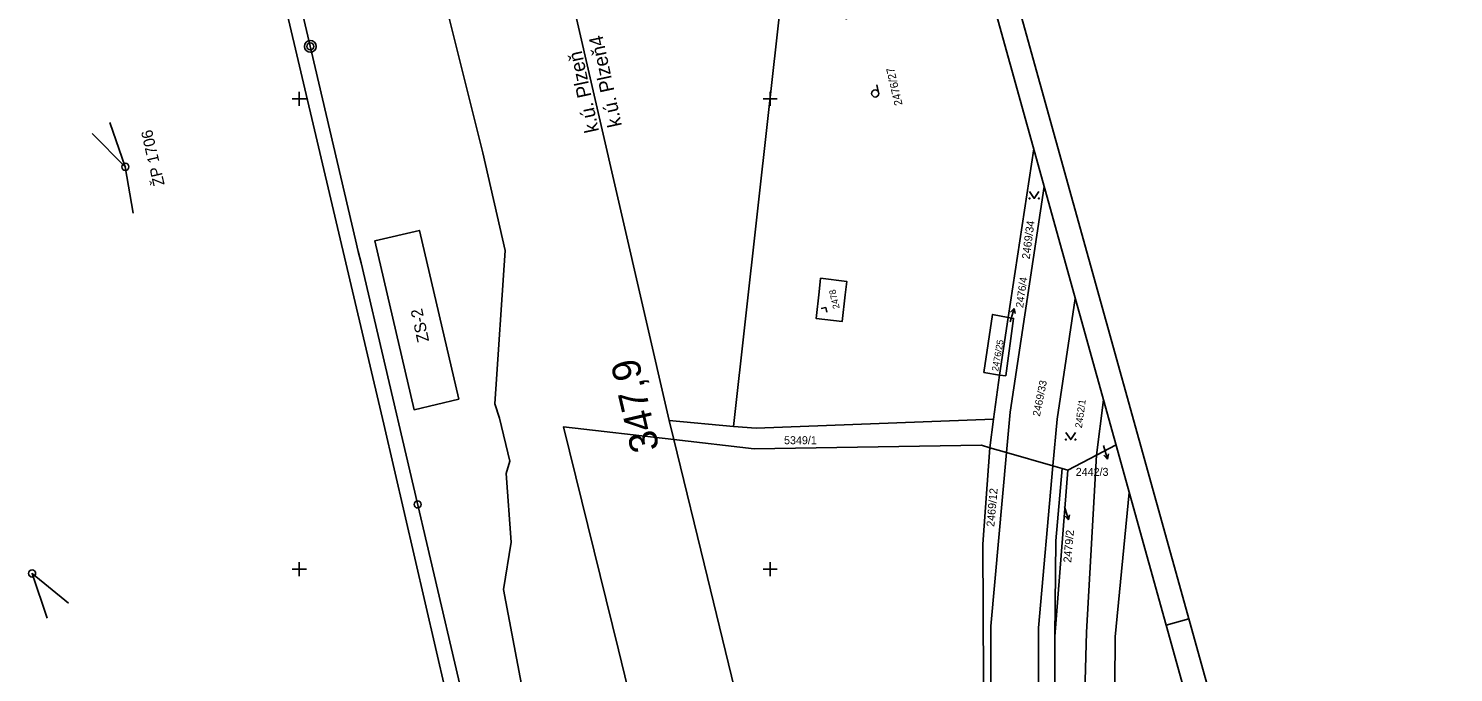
# Model space of a CAD drawing. Extents: x -821122 to -820555, y -1070892 to -1069801.
# Drawn here: x -820857.5 to -820554.8, y -1070622 to -1070485 of the extents above; entities that cross this region are included whole.
import ezdxf

# ---------------------------------------------------------------- set-up
doc = ezdxf.new("R2010")
doc.units = 0
for name, color, linetype in [('Hranice drážního pozemku', 7, 'Continuous'), ('Hranice kat_území', 7, 'Continuous'), ('Hranice parcel', 7, 'Continuous'), ('Katastrální hranice', 7, 'Continuous'), ('Osa staničení koleje', 7, 'Continuous'), ('Parcelní čísla', 7, 'Continuous'), ('Pop  PČ popisy', 7, 'Continuous'), ('Ram', 7, 'Continuous'), ('Sttaniceni a namezniky', 7, 'Continuous'), ('Vrstva 61', 7, 'Continuous'), ('Vrstva 63', 7, 'Continuous'), ('ZBP', 7, 'Continuous'), ('Značky kultur', 7, 'Continuous')]:
    doc.layers.add(name, color=color, linetype=linetype)

msp = doc.modelspace()

# ---------------------------------------------------------------- linework, layer by layer
at = {"layer": 'Hranice drážního pozemku'}
for p, q in [((-820751, -1070439.83), (-820721.42, -1070568.42)), ((-820721.42, -1070568.42), (-820720.44, -1070572.46))]:
    msp.add_line(p, q, dxfattribs=at)
msp.add_lwpolyline([(-820720.44, -1070572.46), (-820743.88, -1070569.76), (-820732.22, -1070617.16), (-820718.37, -1070673.87), (-820707.85, -1070716.96), (-820694.56, -1070770.81), (-820679.24, -1070835.68), (-820677.73, -1070841.82)], dxfattribs=at)
at = {"layer": 'Hranice parcel'}
for p, q in [((-820649.43, -1070546.51), (-820651.29, -1070558.74)), ((-820652.51, -1070568.14), (-820651.29, -1070558.74)), ((-820707.79, -1070569.63), (-820721.42, -1070568.42)), ((-820652.51, -1070568.14), (-820653.29, -1070574.2)), ((-820636.74, -1070578.97), (-820639.52, -1070614.28))]:
    msp.add_line(p, q, dxfattribs=at)
for points in [[(-820707.79, -1070569.63), (-820697.8, -1070480), (-820683.7, -1070483), (-820674.9, -1070430.61)], [(-820649.43, -1070546.51), (-820643.99, -1070510.67)], [(-820641.78, -1070518.63), (-820649.02, -1070566.6), (-820649.79, -1070575.18)], [(-820689.28, -1070538.15), (-820689.6, -1070541.01), (-820690.24, -1070546.7), (-820684.68, -1070547.33), (-820684.04, -1070541.64), (-820683.72, -1070538.82), (-820689.28, -1070538.15)], [(-820635.16, -1070542.44), (-820639.05, -1070568.09), (-820639.94, -1070578.04)], [(-820649.43, -1070546.51), (-820652.73, -1070545.82), (-820654.58, -1070558.16), (-820651.29, -1070558.74)], [(-820649.43, -1070546.51), (-820648.26, -1070546.67), (-820649.94, -1070558.89), (-820651.29, -1070558.74)], [(-820630.65, -1070575.77), (-820629.17, -1070564.01)], [(-820720.44, -1070572.46), (-820743.88, -1070569.76), (-820732.22, -1070617.16), (-820718.37, -1070673.87), (-820707.85, -1070716.96), (-820694.56, -1070770.81), (-820679.24, -1070835.68), (-820677.73, -1070841.82)], [(-820652.51, -1070568.14), (-820702.97, -1070570.05), (-820707.79, -1070569.63)], [(-820644.99, -1070832.73), (-820651.05, -1070805.08), (-820667.4, -1070753.6), (-820685.24, -1070696.04), (-820706.9, -1070628.02), (-820713.28, -1070601.74), (-820720.44, -1070572.46)], [(-820653.29, -1070574.2), (-820654.8, -1070594.7), (-820654.5, -1070652.3), (-820649.6, -1070705.8), (-820646, -1070731.8), (-820634.1, -1070778.9)], [(-820649.79, -1070575.18), (-820653.1, -1070612.1), (-820653, -1070661.95), (-820650.17, -1070690.23), (-820645.27, -1070726.49), (-820637.71, -1070758.5), (-820633.34, -1070773.88)], [(-820610.37, -1070789.85), (-820621.01, -1070753.33), (-820626.77, -1070725.67), (-820631.06, -1070692.78), (-820633.95, -1070654.83), (-820632.82, -1070613.38), (-820630.65, -1070575.77)], [(-820617.78, -1070779.43), (-820623.84, -1070770.91), (-820627.97, -1070756.18), (-820634.95, -1070726.51), (-820640.2, -1070689.19), (-820643, -1070662.1), (-820643, -1070612.5), (-820639.94, -1070578.04)], [(-820639.52, -1070614.28), (-820639.3, -1070594), (-820637.98, -1070578.61)], [(-820639.52, -1070614.28), (-820639.34, -1070655.55), (-820636.46, -1070693.5), (-820631.68, -1070726.33), (-820625.08, -1070753.87), (-820617.78, -1070779.43)]]:
    msp.add_lwpolyline(points, dxfattribs=at)
at = {"layer": 'Katastrální hranice'}
for p, q in [((-820721.42, -1070568.42), (-820751, -1070439.83)), ((-820720.44, -1070572.46), (-820721.42, -1070568.42)), ((-820703.4, -1070574.43), (-820720.44, -1070572.46)), ((-820655.09, -1070573.64), (-820703.4, -1070574.43)), ((-820653.29, -1070574.2), (-820655.09, -1070573.64)), ((-820649.79, -1070575.18), (-820653.29, -1070574.2)), ((-820639.94, -1070578.04), (-820649.79, -1070575.18)), ((-820636.74, -1070578.97), (-820630.65, -1070575.77)), ((-820626.51, -1070573.59), (-820630.65, -1070575.77)), ((-820637.98, -1070578.61), (-820639.94, -1070578.04)), ((-820636.74, -1070578.97), (-820637.98, -1070578.61))]:
    msp.add_line(p, q, dxfattribs=at)
msp.add_lwpolyline([(-820594.11, -1070818.59), (-820613.15, -1070751.36), (-820619.68, -1070724.73), (-820624.16, -1070691.86), (-820626.98, -1070654.7), (-820626.67, -1070614.41), (-820623.69, -1070583.73)], dxfattribs=at)
at = {"layer": 'Osa staničení koleje'}
msp.add_lwpolyline([(-820761.02, -1070645.41), (-820786.89, -1070534.87), (-820787.46, -1070532.43), (-820788.03, -1070530), (-820808.6, -1070442.09), (-820809.13, -1070439.8), (-820809.67, -1070437.51), (-820820.71, -1070390.32)], dxfattribs=at)
at = {"layer": 'Parcelní čísla'}
for p, q in [((-820629.15, -1070573.7), (-820628.31, -1070576.58)), ((-820628.31, -1070576.58), (-820629.08, -1070575.76)), ((-820628.31, -1070576.58), (-820628.11, -1070575.48)), ((-820637.43, -1070586.64), (-820636.59, -1070589.52)), ((-820636.59, -1070589.52), (-820636.39, -1070588.42)), ((-820636.59, -1070589.52), (-820637.35, -1070588.7))]:
    msp.add_line(p, q, dxfattribs=at)
at = {"layer": 'Pop  PČ popisy'}
for p, q in [((-820649.03, -1070547.43), (-820648.15, -1070544.56)), ((-820648.15, -1070544.56), (-820648.92, -1070545.37)), ((-820648.15, -1070544.56), (-820647.97, -1070545.66))]:
    msp.add_line(p, q, dxfattribs=at)
at = {"layer": 'Ram'}
msp.add_line((-820611.05, -1070610.53), (-820615.87, -1070611.87), dxfattribs=at)
for points in [[(-820835.94, -1069801.19), (-820554.83, -1070812.86)], [(-820839.42, -1069807.35), (-820560.99, -1070809.39)]]:
    msp.add_lwpolyline(points, dxfattribs=at)
at = {"layer": 'Sttaniceni a namezniky'}
for centre, radius in [((-820797.65, -1070488.86), 1.25), ((-820797.65, -1070488.86), 0.752), ((-820774.87, -1070586.23), 0.75)]:
    msp.add_circle(centre, radius, dxfattribs=at)
at = {"layer": 'Vrstva 61'}
for p, q in [((-820801.5, -1070500), (-820798.5, -1070500)), ((-820800, -1070498.5), (-820800, -1070501.5)), ((-820701.5, -1070500), (-820698.5, -1070500)), ((-820700, -1070498.5), (-820700, -1070501.5)), ((-820801.5, -1070600), (-820798.5, -1070600)), ((-820800, -1070598.5), (-820800, -1070601.5)), ((-820701.5, -1070600), (-820698.5, -1070600)), ((-820700, -1070598.5), (-820700, -1070601.5))]:
    msp.add_line(p, q, dxfattribs=at)
at = {"layer": 'Vrstva 63'}
for points in [[(-820782.06, -1070569.19), (-820823.93, -1070391.03)], [(-820774.11, -1070459), (-820761.04, -1070511.47), (-820756.27, -1070532.22), (-820758.47, -1070564.86)], [(-820758.47, -1070564.86), (-820757.45, -1070567.88), (-820755.31, -1070577.01), (-820756.05, -1070579.63), (-820755.02, -1070594.22), (-820756.59, -1070604.3), (-820752.56, -1070625.64)], [(-820766.7, -1070635.67), (-820782.06, -1070569.19)]]:
    msp.add_lwpolyline(points, dxfattribs=at)
msp.add_lwpolyline([(-820766.13, -1070563.88), (-820775.61, -1070566.1), (-820783.95, -1070530.19), (-820774.47, -1070527.98)], close=True, dxfattribs=at)
at = {"layer": 'ZBP'}
for p, q in [((-820836.96, -1070514.46), (-820840.27, -1070505.03)), ((-820836.96, -1070514.46), (-820843.98, -1070507.35)), ((-820836.94, -1070514.51), (-820836.97, -1070514.41)), ((-820836.96, -1070514.46), (-820835.31, -1070524.32)), ((-820856.75, -1070600.96), (-820856.77, -1070600.87)), ((-820856.76, -1070600.91), (-820848.99, -1070607.21)), ((-820856.76, -1070600.91), (-820853.52, -1070610.38))]:
    msp.add_line(p, q, dxfattribs=at)
for centre in [(-820836.96, -1070514.46), (-820856.76, -1070600.91)]:
    msp.add_circle(centre, 0.756, dxfattribs=at)
at = {"layer": 'Značky kultur'}
for p, q in [((-820676.94, -1070498.7), (-820677.34, -1070497)), ((-820688.16, -1070544.37), (-820689.13, -1070544.6)), ((-820687.93, -1070545.35), (-820688.16, -1070544.37))]:
    msp.add_line(p, q, dxfattribs=at)
for points in [[(-820644.89, -1070519.69), (-820643.89, -1070521.19), (-820642.89, -1070519.69)], [(-820637.15, -1070570.96), (-820636.15, -1070572.46), (-820635.15, -1070570.96)]]:
    msp.add_lwpolyline(points, dxfattribs=at)
for centre, radius in [((-820677.67, -1070498.87), 0.75), ((-820644.89, -1070521.19), 0.1), ((-820642.89, -1070521.19), 0.1), ((-820637.15, -1070572.46), 0.1), ((-820635.15, -1070572.46), 0.1)]:
    msp.add_circle(centre, radius, dxfattribs=at)

# ---------------------------------------------------------------- texts
at = {"layer": 'Hranice kat_území'}
for s, p in [('k.ú. Plzeň4', (-820731.45, -1070505.71)), ('k.ú. Plzeň', (-820736.32, -1070506.87))]:
    msp.add_text(s, height=3, rotation=102.1429, dxfattribs=at).set_placement(p)
at = {"layer": 'Parcelní čísla'}
for s, height, rotation, p in [('2476/27', 1.7, 103, (-820671.85, -1070501.24)), ('2469/34', 1.7, 82.5816, (-820644.86, -1070534.17)), ('2476/4', 1.6, 82, (-820646.25, -1070544.51)), ('2478', 1.4, 103, (-820685.2, -1070544.49)), ('2476/25', 1.4, 80, (-820651.56, -1070558.01)), ('2469/33', 1.6, 78.6983, (-820642.69, -1070567.61)), ('2452/1', 1.5, 82.2761, (-820633.76, -1070570.07)), ('2469/12', 1.7, 85, (-820652.37, -1070591.04)), ('2479/2', 1.7, 85, (-820636.04, -1070598.66))]:
    msp.add_text(s, height=height, rotation=rotation, dxfattribs=at).set_placement(p)
for s, p in [('5349/1', (-820697.03, -1070573.43)), ('2442/3', (-820635.07, -1070580.16))]:
    msp.add_text(s, height=1.7, dxfattribs=at).set_placement(p)
at = {"layer": 'Sttaniceni a namezniky'}
msp.add_text('347,9', height=6, rotation=103.1701, dxfattribs=at).set_placement((-820723.49, -1070574.37))
at = {"layer": 'Vrstva 63'}
msp.add_text('ZS-2', height=2.5, rotation=102.2938, dxfattribs=at).set_placement((-820772.4, -1070551.48))
at = {"layer": 'ZBP'}
msp.add_text('ŽP 1706', height=2.4, rotation=103, dxfattribs=at).set_placement((-820828.58, -1070518.23))

doc.saveas('drawing.dxf')
